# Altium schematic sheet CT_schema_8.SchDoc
size 277 x 170 mm
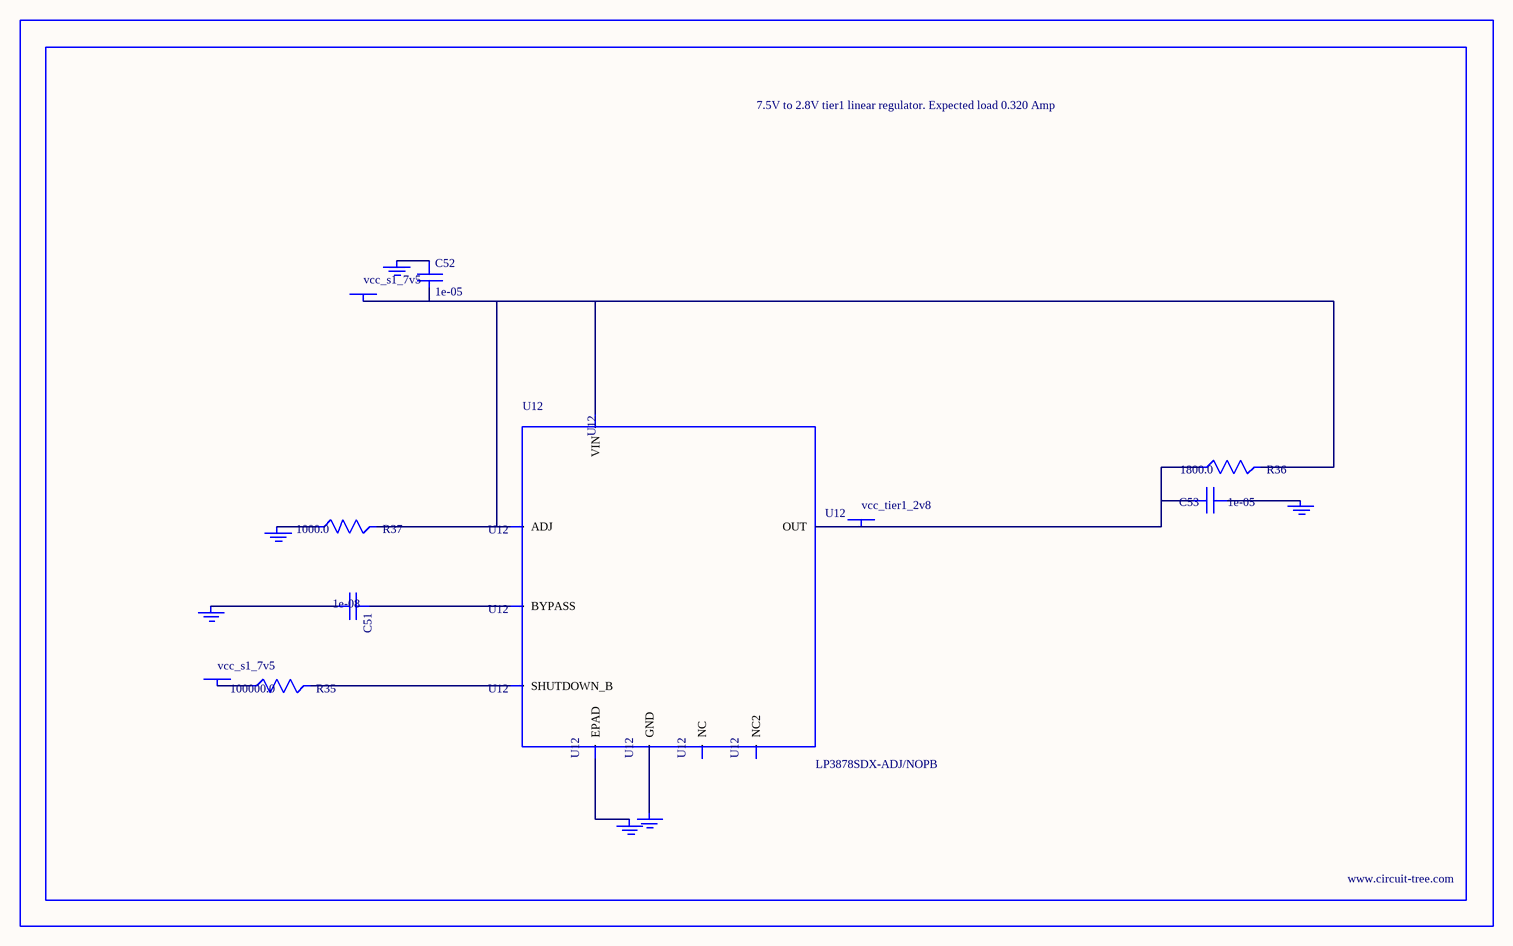
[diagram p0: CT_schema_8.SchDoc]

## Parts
BORDER7  (no value)
C51  1e-08  [C0402]
C52  1e-05  [C1206]
C53  1e-05  [C1210]
GND_INSTANCE_7_0  (no value)
GND_INSTANCE_7_1  (no value)
GND_INSTANCE_7_2  (no value)
GND_INSTANCE_7_3  (no value)
GND_INSTANCE_7_4  (no value)
GND_INSTANCE_7_5  (no value)
POWER_INSTANCE_7_0  vcc_s1_7v5
POWER_INSTANCE_7_1  vcc_s1_7v5
POWER_INSTANCE_7_2  vcc_tier1_2v8
R35  100000.0  [R0603]
R36  1800.0  [R0603]
R37  1000.0  [R0603]
U12  LP3878SDX-ADJ/NOPB  [WSON-8]

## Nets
NetC51_1: C51.1 U12.1(BYPASS)
NetC51_2: C51.2 GND_INSTANCE_7_0.0(GND)
NetC52_1: C52.1 GND_INSTANCE_7_1.0(GND)
NetC52_2: C52.2 POWER_INSTANCE_7_0.0(PWR) R36.2 R37.2 U12.4(VIN) U12.6(ADJ)
NetC53_1: C53.1 GND_INSTANCE_7_2.0(GND)
NetC53_2: C53.2 POWER_INSTANCE_7_2.0(PWR) R36.1 U12.5(OUT)
NetGND_INSTANCE_7_3_0: GND_INSTANCE_7_3.0(GND) R37.1
NetGND_INSTANCE_7_4_0: GND_INSTANCE_7_4.0(GND) U12.PAD(EPAD)
NetGND_INSTANCE_7_5_0: GND_INSTANCE_7_5.0(GND) U12.3(GND)
NetPOWER_INSTANCE_7_1_0: POWER_INSTANCE_7_1.0(PWR) R35.1
NetR35_2: R35.2 U12.8(SHUTDOWN_B)

Not connected (* = marked no-connect by the designer): U12 2(NC) 7(NC2)

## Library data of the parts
BORDER7 = BORDER_PAGE7
C51 = C0402C103K3RAC
C52 = C1206C106K3RACTU
C53 = GRM32DR61E106MA12L
GND_INSTANCE_7_0-GND_INSTANCE_7_5 = GND
POWER_INSTANCE_7_0-POWER_INSTANCE_7_2 = PWR
R35 = RC0603JR-07100KL
R36 = RC0603JR-071K8L
R37 = RC0603JR-071KL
